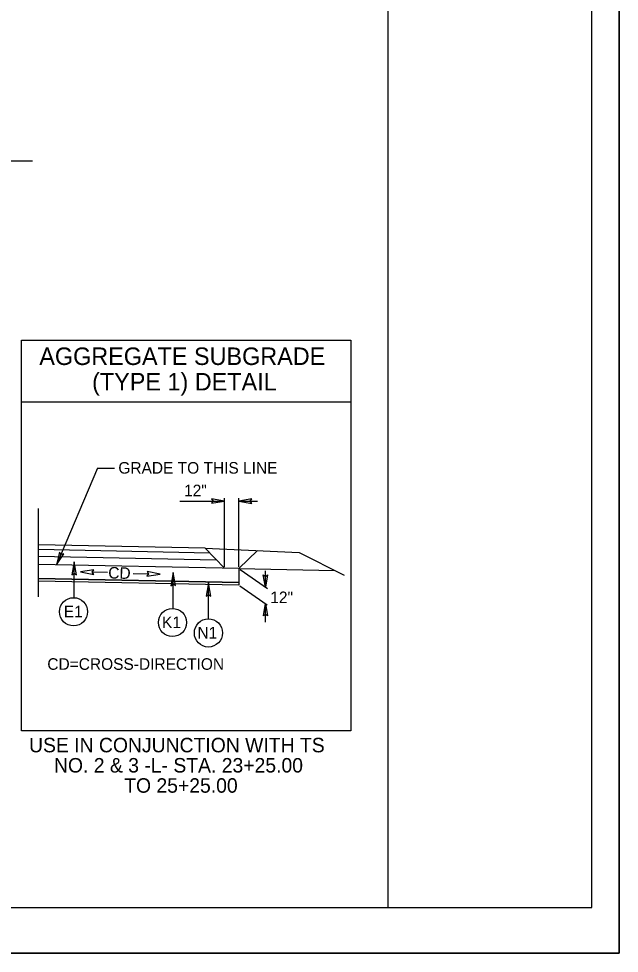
# Model space of a CAD drawing. Extents: x 1184121 to 1184397, y 1246506 to 1246661.
# Drawn here: x 1184318.8 to 1184360.3, y 1246505.7 to 1246570.3 of the extents above; entities that cross this region are included whole.
import ezdxf

# ---------------------------------------------------------------- set-up
doc = ezdxf.new("R2010")
doc.units = 0
for name, color, linetype in [('Prop Dimension', 7, 'Continuous'), ('Prop Dimension Text', 7, 'Continuous'), ('Prop Terminator CELL', 7, 'Continuous'), ('Sheet Data Field CELL', 7, 'Continuous'), ('Sheet Plan CELL', 7, 'Continuous'), ('Sheet Plot Border Outside CELL', 7, 'Continuous'), ('Typical Hinge Slope Interstate CELL', 7, 'Continuous'), ('Typical ID Circle CELL', 7, 'Continuous'), ('Typical Pavement Slope CELL', 7, 'Continuous'), ('Typical Shoulder Slope CELL', 7, 'Continuous'), ('Typical Terminator CELL', 7, 'Continuous'), ('Typical Text General CELL', 7, 'Continuous'), ('Typical Text Label CELL', 7, 'Continuous'), ('z - Construction', 7, 'Continuous')]:
    doc.layers.add(name, color=color, linetype=linetype)

msp = doc.modelspace()

# ---------------------------------------------------------------- linework, layer by layer
at = {"layer": 'Prop Dimension'}
for p, q in [((1184324.266, 1246539.218), (1184321.434, 1246532.537)), ((1184324.266, 1246539.218), (1184325.45, 1246539.218)), ((1184320.19, 1246530.326), (1184320.19, 1246536.424)), ((1184324.963, 1246532.007), (1184323.896, 1246532.034)), ((1184326.732, 1246531.942), (1184327.799, 1246531.915))]:
    msp.add_line(p, q, dxfattribs=at)
at = {"layer": 'Prop Dimension Text'}
for p, q in [((1184329.955, 1246536.936), (1184333.031, 1246536.936)), ((1184333.031, 1246532.404), (1184333.031, 1246537.138)), ((1184334.031, 1246532.404), (1184334.031, 1246537.138)), ((1184334.031, 1246536.936), (1184335.322, 1246536.936)), ((1184334.126, 1246532.219), (1184336.007, 1246530.901)), ((1184335.873, 1246530.995), (1184335.873, 1246532.128)), ((1184334.102, 1246531.093), (1184335.978, 1246529.779)), ((1184335.87, 1246528.569), (1184335.87, 1246529.855))]:
    msp.add_line(p, q, dxfattribs=at)
at = {"layer": 'Prop Terminator CELL'}
for points in [[(1184336.018, 1246531.839), (1184335.873, 1246530.995), (1184335.723, 1246531.844), (1184335.873, 1246531.736)], [(1184335.724, 1246529.011), (1184335.87, 1246529.855), (1184336.02, 1246529.007), (1184335.87, 1246529.115)]]:
    msp.add_lwpolyline(points, close=True, dxfattribs=at)
at = {"layer": 'Sheet Data Field CELL'}
msp.add_line((1184293.343, 1246560.441), (1184319.777, 1246560.441), dxfattribs=at)
for points in [[(1184322.812, 1246531.84), (1184322.655, 1246532.749), (1184322.493, 1246531.835), (1184322.655, 1246531.951)], [(1184324.011, 1246532.188), (1184323.098, 1246532.055), (1184324.008, 1246531.869), (1184323.896, 1246532.034)], [(1184327.684, 1246531.761), (1184328.597, 1246531.894), (1184327.687, 1246532.079), (1184327.799, 1246531.915)], [(1184329.65, 1246531.099), (1184329.493, 1246532.009), (1184329.331, 1246531.094), (1184329.493, 1246531.21)], [(1184332.09, 1246530.38), (1184331.933, 1246531.29), (1184331.772, 1246530.375), (1184331.933, 1246530.491)]]:
    msp.add_lwpolyline(points, close=True, dxfattribs=at)
for centre in [(1184322.608, 1246529.293), (1184329.446, 1246528.553), (1184331.928, 1246527.832)]:
    msp.add_circle(centre, 0.972, dxfattribs=at)
at = {"layer": 'Sheet Plan CELL'}
for p, q in [((1184344.345, 1246508.875), (1184344.348, 1246657.364)), ((1184358.419, 1246508.875), (1184358.423, 1246657.364)), ((1184126.181, 1246508.875), (1184358.419, 1246508.875))]:
    msp.add_line(p, q, dxfattribs=at)
at = {"layer": 'Sheet Plot Border Outside CELL'}
msp.add_lwpolyline([(1184121.05, 1246660.53), (1184360.324, 1246660.53), (1184360.324, 1246505.708), (1184121.05, 1246505.708)], close=True, dxfattribs=at)
at = {"layer": 'Typical Hinge Slope Interstate CELL'}
msp.add_line((1184338.203, 1246533.386), (1184341.314, 1246531.83), dxfattribs=at)
msp.add_lwpolyline([(1184320.193, 1246531.592), (1184334.035, 1246531.315), (1184334.031, 1246531.142), (1184320.19, 1246531.419)], close=True, dxfattribs=at)
at = {"layer": 'Typical ID Circle CELL'}
for p, q in [((1184322.655, 1246530.264), (1184322.655, 1246532.749)), ((1184329.493, 1246529.524), (1184329.493, 1246532.009)), ((1184331.933, 1246528.804), (1184331.933, 1246531.29))]:
    msp.add_line(p, q, dxfattribs=at)
at = {"layer": 'Typical Pavement Slope CELL'}
for p, q in [((1184332.03, 1246533.348), (1184320.183, 1246533.585)), ((1184331.706, 1246533.685), (1184320.19, 1246533.915)), ((1184332.499, 1246532.859), (1184320.174, 1246533.106)), ((1184334.031, 1246532.285), (1184320.19, 1246532.562)), ((1184334.035, 1246531.315), (1184320.193, 1246531.592))]:
    msp.add_line(p, q, dxfattribs=at)
at = {"layer": 'Typical Shoulder Slope CELL'}
for p, q in [((1184331.706, 1246533.685), (1184338.203, 1246533.386)), ((1184333.031, 1246532.305), (1184331.706, 1246533.685)), ((1184335.315, 1246533.518), (1184334.031, 1246532.285)), ((1184334.031, 1246532.285), (1184334.031, 1246531.315)), ((1184334.031, 1246532.285), (1184340.669, 1246532.152)), ((1184334.031, 1246531.142), (1184320.19, 1246531.419))]:
    msp.add_line(p, q, dxfattribs=at)
at = {"layer": 'Typical Terminator CELL'}
for points in [[(1184332.141, 1246536.783), (1184333.031, 1246536.936), (1184332.136, 1246537.095), (1184332.25, 1246536.936)], [(1184334.922, 1246537.09), (1184334.031, 1246536.936), (1184334.927, 1246536.778), (1184334.813, 1246536.936)], [(1184321.644, 1246533.402), (1184321.434, 1246532.537), (1184321.927, 1246533.284), (1184321.74, 1246533.243)]]:
    msp.add_lwpolyline(points, close=True, dxfattribs=at)
at = {"layer": 'Typical Text Label CELL'}
msp.add_line((1184319.024, 1246543.8), (1184341.771, 1246543.8), dxfattribs=at)
msp.add_lwpolyline([(1184319.024, 1246548.062), (1184341.771, 1246548.062), (1184341.771, 1246521.07), (1184319.024, 1246521.07)], close=True, dxfattribs=at)
at = {"layer": 'z - Construction'}
for p, q in [((1184360.324, 1246505.708), (1184360.324, 1246660.53)), ((1184121.05, 1246505.708), (1184360.324, 1246505.708))]:
    msp.add_line(p, q, dxfattribs=at)

# ---------------------------------------------------------------- texts
at = {"layer": 'Prop Dimension Text'}
for p in [(1184330.248, 1246537.271), (1184336.206, 1246529.891)]:
    msp.add_text('12"', height=0.8, dxfattribs=at).set_placement(p)
at = {"layer": 'Sheet Data Field CELL'}
for s, height, p in [('AGGREGATE SUBGRADE', 1.20892, (1184320.242, 1246546.337)), ('(TYPE 1) DETAIL', 1.20892, (1184323.89, 1246544.579)), ('E1', 0.8, (1184321.936, 1246528.908)), ('K1', 0.8, (1184328.724, 1246528.167)), ('N1', 0.8, (1184331.172, 1246527.447))]:
    msp.add_text(s, height=height, dxfattribs=at).set_placement(p)
for s, p in [('USE IN CONJUNCTION WITH TS', (1184319.534, 1246519.588)), ('NO. 2 & 3 -L- STA. 23+25.00', (1184321.257, 1246518.193)), ('TO 25+25.00', (1184326.108, 1246516.798))]:
    msp.add_text(s, height=1, rotation=0.00023, dxfattribs=at).set_placement(p)
at = {"layer": 'Typical Hinge Slope Interstate CELL'}
msp.add_text('CD', height=0.8, rotation=358.53136, dxfattribs=at).set_placement((1184325, 1246531.595))
msp.add_text('CD=CROSS-DIRECTION', height=0.8, dxfattribs=at).set_placement((1184320.798, 1246525.285))
at = {"layer": 'Typical Text General CELL'}
msp.add_text('GRADE TO THIS LINE', height=0.8, dxfattribs=at).set_placement((1184325.704, 1246538.833))

doc.saveas('drawing.dxf')
